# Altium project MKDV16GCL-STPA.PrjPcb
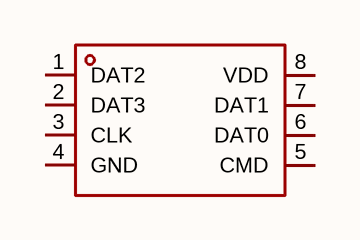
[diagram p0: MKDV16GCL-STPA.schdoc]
1 sheet, 1 parts. Net scope: global (net labels, ports and power ports of the same name join across sheets).

## Sheet MKDV16GCL-STPA.schdoc
size 127 x 101 mm

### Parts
U?  mkdv16gcl-stpa  [LGA-8_L8.0-W6.0-P1.27-TL_MKDV4GCL-ABF]  (value not drawn)

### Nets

Not connected (* = marked no-connect by the designer): U? 1(DAT2) 2(DAT3) 3(CLK) 4(GND) 5(CMD) 6(DAT0) 7(DAT1) 8(VDD)

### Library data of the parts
U? = mkdv16gcl-stpa: 存储容量:16Gbit;时钟频率(fc):50MHz;工作电压:2.7V~3.6V;; Manufacturer: MK(米客方德); AddInBom: yes; ModelId: ef50f8f4e0d745e797621e4f42c5cff2; ModelTransform: 314.96,236.22,0,0,0,0,0,0,0; Memory Size: 16Gbit; Interface: SPI; Clock Frequency: 50MHz; Standby Supply Current: 190uA; Program / Erase Cycles: 5千次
